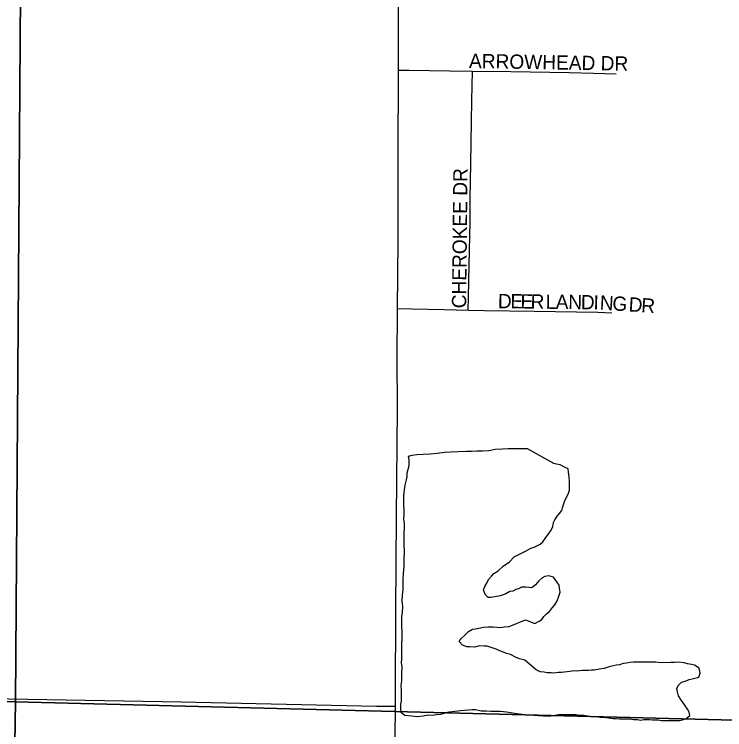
# Model space of a CAD drawing. Extents: x 0 to 68, y 0 to 52.9.
# Drawn here: x 44.473 to 45.094, y 39.226 to 39.851 of the extents above; entities that cross this region are included whole.
import ezdxf

# ---------------------------------------------------------------- set-up
doc = ezdxf.new("R2010")
doc.units = 0
for name, color, linetype in [('Default', 7, 'Continuous'), ('GM_X_Minor_Lake', 7, 'Continuous'), ('GM_X_Township_Road', 7, 'Continuous'), ('GM_X_Township_Subdivision', 7, 'Continuous'), ('GM_X_Township_Subdivision_Text', 7, 'Continuous')]:
    doc.layers.add(name, color=color, linetype=linetype)

msp = doc.modelspace()

# ---------------------------------------------------------------- linework, layer by layer
at = {"layer": 'Default'}
for points in [[(44.48288, 40.57177), (44.47349, 39.25009), (43.1609, 39.26536), (43.18329, 40.58736)], [(44.48288, 40.57177), (45.8139, 40.54118), (45.79985, 39.21605), (44.47349, 39.25009)], [(43.1609, 39.26536), (44.47349, 39.25009), (44.45233, 37.93902), (44.41032, 37.93957), (43.13273, 37.95279)], [(45.79985, 39.21605), (45.7821, 37.90702), (45.7586, 37.9073), (44.45233, 37.93902), (44.47349, 39.25009)]]:
    msp.add_lwpolyline(points, close=True, dxfattribs=at)
at = {"layer": 'GM_X_Minor_Lake'}
for points in [[(44.92157, 39.47115), (44.90769, 39.47127), (44.90468, 39.47133), (44.89965, 39.47093), (44.89313, 39.47056), (44.88759, 39.46967), (44.88206, 39.46928), (44.87705, 39.46938), (44.87252, 39.46897), (44.86801, 39.46906), (44.86098, 39.4687), (44.85445, 39.46833), (44.84893, 39.46794), (44.84239, 39.46707), (44.83636, 39.46669), (44.83033, 39.46631), (44.82481, 39.46592), (44.82028, 39.46551), (44.81725, 39.46457), (44.8177, 39.46205), (44.81765, 39.45955), (44.8176, 39.45704), (44.81704, 39.45404), (44.81596, 39.45005), (44.81589, 39.44704), (44.81533, 39.44405), (44.81424, 39.43956), (44.81365, 39.43555), (44.81305, 39.43055), (44.81297, 39.42654), (44.81321, 39.4135), (44.81314, 39.40999), (44.81356, 39.40597), (44.81348, 39.40196), (44.81339, 39.39795), (44.81329, 39.39293), (44.81319, 39.38792), (44.81355, 39.38089), (44.81344, 39.37538), (44.8133, 39.36836), (44.81267, 39.36236), (44.81256, 39.35684), (44.81248, 39.35283), (44.81239, 39.34832), (44.81178, 39.34331), (44.81168, 39.3383), (44.81208, 39.33328), (44.81198, 39.32826), (44.81141, 39.32477), (44.81132, 39.32025), (44.81124, 39.31624), (44.81164, 39.31122), (44.81152, 39.30571), (44.81142, 39.30069), (44.81132, 39.29568), (44.81122, 39.29067), (44.81115, 39.28716), (44.81109, 39.28415), (44.81152, 39.28063), (44.81141, 39.27512), (44.81127, 39.2686), (44.81068, 39.2641), (44.81111, 39.26058), (44.81106, 39.25807), (44.81098, 39.25406), (44.81091, 39.25055), (44.81035, 39.24806), (44.81027, 39.24405), (44.81072, 39.24103), (44.81417, 39.23845), (44.82018, 39.23783), (44.82468, 39.23723), (44.83021, 39.23763), (44.83474, 39.23854), (44.83875, 39.23846), (44.84177, 39.2389), (44.8458, 39.23932), (44.85286, 39.24118), (44.86292, 39.24248), (44.86995, 39.24284), (44.87297, 39.24328), (44.87598, 39.24322), (44.88097, 39.24212), (44.88548, 39.24203), (44.88949, 39.24195), (44.892, 39.2419), (44.89501, 39.24184), (44.89802, 39.24178), (44.90302, 39.24117), (44.90702, 39.24059), (44.91002, 39.24003), (44.91869, 39.23903)], [(44.92035, 39.38207), (44.92435, 39.38443), (44.92739, 39.38539), (44.93245, 39.38784), (44.935, 39.38981), (44.93705, 39.3928), (44.94012, 39.39728), (44.94218, 39.40026), (44.94373, 39.40326), (44.94427, 39.40677), (44.94531, 39.40926), (44.94736, 39.41225), (44.94941, 39.41473), (44.95145, 39.41722), (44.95199, 39.41972), (44.95356, 39.42422), (44.9546, 39.42672), (44.95717, 39.43171), (44.95822, 39.43521), (44.95826, 39.43822), (44.95832, 39.44274), (44.95787, 39.44677), (44.95741, 39.45079), (44.95695, 39.45381), (44.95395, 39.45536), (44.94995, 39.45742), (44.94693, 39.45796), (44.94442, 39.4585), (44.92157, 39.47115)], [(44.92007, 39.35032), (44.91928, 39.35018), (44.91928, 39.35018), (44.91627, 39.35024), (44.91373, 39.34878), (44.91122, 39.34833), (44.90868, 39.34688), (44.90616, 39.34643), (44.90261, 39.34449), (44.90008, 39.34354), (44.89755, 39.34259), (44.89302, 39.34168), (44.8895, 39.34125), (44.88699, 39.3413), (44.88454, 39.34385), (44.88311, 39.34789), (44.88418, 39.35088), (44.88625, 39.35435), (44.88731, 39.35684), (44.88987, 39.3598), (44.89193, 39.36226), (44.89599, 39.36469), (44.90009, 39.36862), (44.90568, 39.37252), (44.90979, 39.37695), (44.92035, 39.38207)], [(44.91972, 39.32174), (44.92806, 39.31858), (44.93161, 39.32055), (44.93414, 39.32202), (44.93568, 39.32451), (44.93823, 39.32699), (44.94078, 39.32896), (44.94334, 39.33244), (44.94538, 39.33493), (44.94744, 39.33842), (44.949, 39.34242), (44.95005, 39.34592), (44.94959, 39.34944), (44.94912, 39.35196), (44.94715, 39.355), (44.94418, 39.35905), (44.94016, 39.36011), (44.93663, 39.35965), (44.93409, 39.35818), (44.93154, 39.3557), (44.92848, 39.35223), (44.92543, 39.34976), (44.92007, 39.35032)], [(44.91926, 39.28629), (44.9145, 39.28758), (44.91102, 39.28916), (44.90655, 39.29125), (44.90306, 39.29233), (44.89659, 39.29497), (44.8941, 39.29602), (44.89061, 39.29709), (44.88613, 39.29869), (44.88362, 39.29874), (44.87961, 39.29882), (44.87508, 39.29791), (44.87106, 39.29799), (44.86856, 39.29804), (44.86458, 39.29962), (44.86163, 39.30269), (44.86318, 39.30517), (44.86625, 39.30811), (44.86983, 39.31155), (44.87338, 39.31349), (44.8759, 39.31394), (44.87892, 39.31438), (44.88295, 39.3153), (44.88698, 39.31572), (44.89149, 39.31563), (44.89749, 39.31501), (44.90102, 39.31544), (44.90554, 39.31585), (44.91972, 39.32174)], [(44.91869, 39.23903), (44.93963, 39.23757), (44.94416, 39.23801), (44.94871, 39.23896), (44.95122, 39.23892), (44.95425, 39.23889), (44.95878, 39.23882), (44.96129, 39.23879), (44.96381, 39.23876), (44.96733, 39.23821), (44.97085, 39.23817), (44.97387, 39.23762), (44.97688, 39.23708), (44.98141, 39.23702), (44.98493, 39.23647), (44.98795, 39.23643), (44.9965, 39.23532), (44.99901, 39.23528), (45.00204, 39.23524), (45.00506, 39.23521), (45.00858, 39.23516), (45.0111, 39.23513), (45.01461, 39.23458), (45.01764, 39.23454), (45.02065, 39.234), (45.02317, 39.23447), (45.02821, 39.2344), (45.03073, 39.23437), (45.03324, 39.23433), (45.03576, 39.2343), (45.03877, 39.23376), (45.0423, 39.23371), (45.04683, 39.23365), (45.04985, 39.23361), (45.05489, 39.23355), (45.05994, 39.23499), (45.0635, 39.23796), (45.06304, 39.24098), (45.06156, 39.24351), (45.05908, 39.24705), (45.05611, 39.25111), (45.05365, 39.25516), (45.05268, 39.25869), (45.05222, 39.26171), (45.05326, 39.26421), (45.05632, 39.26718), (45.05935, 39.26815), (45.06289, 39.26961), (45.06542, 39.27007), (45.06794, 39.27054), (45.07148, 39.2715), (45.07253, 39.27501), (45.07158, 39.27954), (45.06758, 39.2821), (45.06507, 39.28264), (45.06155, 39.28318), (45.05854, 39.28423), (45.05352, 39.2848), (45.04999, 39.28434), (45.04646, 39.28439), (45.0389, 39.28398), (45.03589, 39.28452), (45.03337, 39.28456), (45.03085, 39.28459), (45.02834, 39.28462), (45.02582, 39.28466), (45.02179, 39.28471), (45.01827, 39.28476), (45.01424, 39.28481), (45.01121, 39.28435), (45.00819, 39.28388), (45.00516, 39.28342), (45.00213, 39.28246), (44.9991, 39.28199), (44.99658, 39.28152), (44.99304, 39.28056), (44.98849, 39.27912), (44.98445, 39.27867), (44.97991, 39.27772), (44.97739, 39.27776), (44.97487, 39.27729), (44.97235, 39.27732), (44.96933, 39.27736), (44.96479, 39.27692), (44.96177, 39.27696), (44.95875, 39.27649), (44.9537, 39.27606), (44.95118, 39.27559), (44.94867, 39.27562), (44.94463, 39.27517), (44.94211, 39.27521), (44.93859, 39.27525), (44.93608, 39.27579), (44.93256, 39.27633), (44.92905, 39.27789), (44.91926, 39.28629)]]:
    msp.add_lwpolyline(points, dxfattribs=at)
at = {"layer": 'GM_X_Township_Road'}
for points in [[(44.80855, 39.80262), (44.80856, 39.81305), (44.80869, 39.97709), (44.8086, 40.02632), (44.80985, 40.29282)], [(44.80784, 39.59407), (44.80844, 39.65308), (44.80851, 39.72692), (44.80855, 39.80262)], [(44.80605, 39.24618), (44.80614, 39.25626), (44.80645, 39.32999), (44.80694, 39.41203), (44.80768, 39.50639), (44.8076, 39.55091), (44.80783, 39.59154), (44.80784, 39.59407)], [(44.1418, 39.25679), (44.16941, 39.2568), (44.26323, 39.25614), (44.36303, 39.25437), (44.46782, 39.2526), (44.61841, 39.24995), (44.78938, 39.24628), (44.80605, 39.24618)], [(44.7872, 37.93047), (44.78916, 38.0655), (44.79016, 38.11876), (44.79071, 38.17209), (44.79244, 38.2459), (44.79316, 38.30333), (44.79602, 38.45915), (44.79696, 38.52068), (44.79793, 38.56987), (44.79919, 38.6847), (44.79993, 38.77083), (44.80072, 38.85276), (44.80196, 38.93851), (44.80314, 39.05312), (44.80377, 39.09415), (44.80406, 39.13866), (44.8054, 39.1908), (44.80605, 39.24618)]]:
    msp.add_lwpolyline(points, dxfattribs=at)
at = {"layer": 'GM_X_Township_Subdivision'}
for points in [[(44.80855, 39.80262), (44.81813, 39.80249), (44.85348, 39.80202), (44.87334, 39.80174)], [(44.86969, 39.59265), (44.86993, 39.60351), (44.87055, 39.63226), (44.87123, 39.67004), (44.87128, 39.68976), (44.87181, 39.72098), (44.87289, 39.77601), (44.87334, 39.80174)], [(44.87334, 39.80174), (44.90691, 39.80125), (44.95787, 39.80039), (44.97923, 39.79998), (44.99895, 39.79923)], [(44.80784, 39.59407), (44.82073, 39.59377), (44.8486, 39.59312), (44.86969, 39.59265)], [(44.86969, 39.59265), (44.88384, 39.59233), (44.92729, 39.59159), (44.98303, 39.59077), (44.99531, 39.59014)]]:
    msp.add_lwpolyline(points, dxfattribs=at)

# ---------------------------------------------------------------- texts
at = {"layer": 'GM_X_Township_Subdivision_Text'}
for s, rotation, p in [('ARROWHEAD DR', 358.99454, (44.87025, 39.80443)), ('CHEROKEE DR', 89.41615, (44.86785, 39.59414)), ('D', 359.27865, (44.89553, 39.59433)), ('E', 359.26233, (44.90652, 39.59419)), ('E', 359.26233, (44.91532, 39.59408)), ('R', 359.26988, (44.92413, 39.59396)), ('L', 359.26585, (44.93732, 39.59379)), ('A', 359.25679, (44.94612, 39.59369)), ('N', 359.27204, (44.95712, 39.59354)), ('D', 359.25679, (44.96812, 39.5934)), ('I', 358.11997, (44.97905, 39.59326)), ('N', 356.69771, (44.98447, 39.59309)), ('G', 356.26007, (44.99542, 39.59245)), ('D', 356.27732, (45.0097, 39.59152)), ('R', 356.25701, (45.02067, 39.59081))]:
    msp.add_text(s, height=0.0125, rotation=rotation, dxfattribs=at).set_placement(p)

doc.saveas('drawing.dxf')
